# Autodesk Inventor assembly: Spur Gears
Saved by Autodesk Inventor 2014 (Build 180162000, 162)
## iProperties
Created: 2010-12
Part Number: Spur Gears
Document SubType Name: Assembly
Designer: Thom Tremblay
Categories: <?xml version="1.0" encoding="UTF-16"?> <MemberInstance><Categories><FamilyTemplate/><ParamToTemplateMap><ParamToTemplate><ParamToTemplate CategoryParameter="//
ClientObjectVersion: 1
Author: Thom Tremblay
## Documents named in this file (1)
- C:\Inventor 2014 Essentials\Assemblies\Chapter 08\c08-01\Design Accelerator\Spur Gears1.iam
